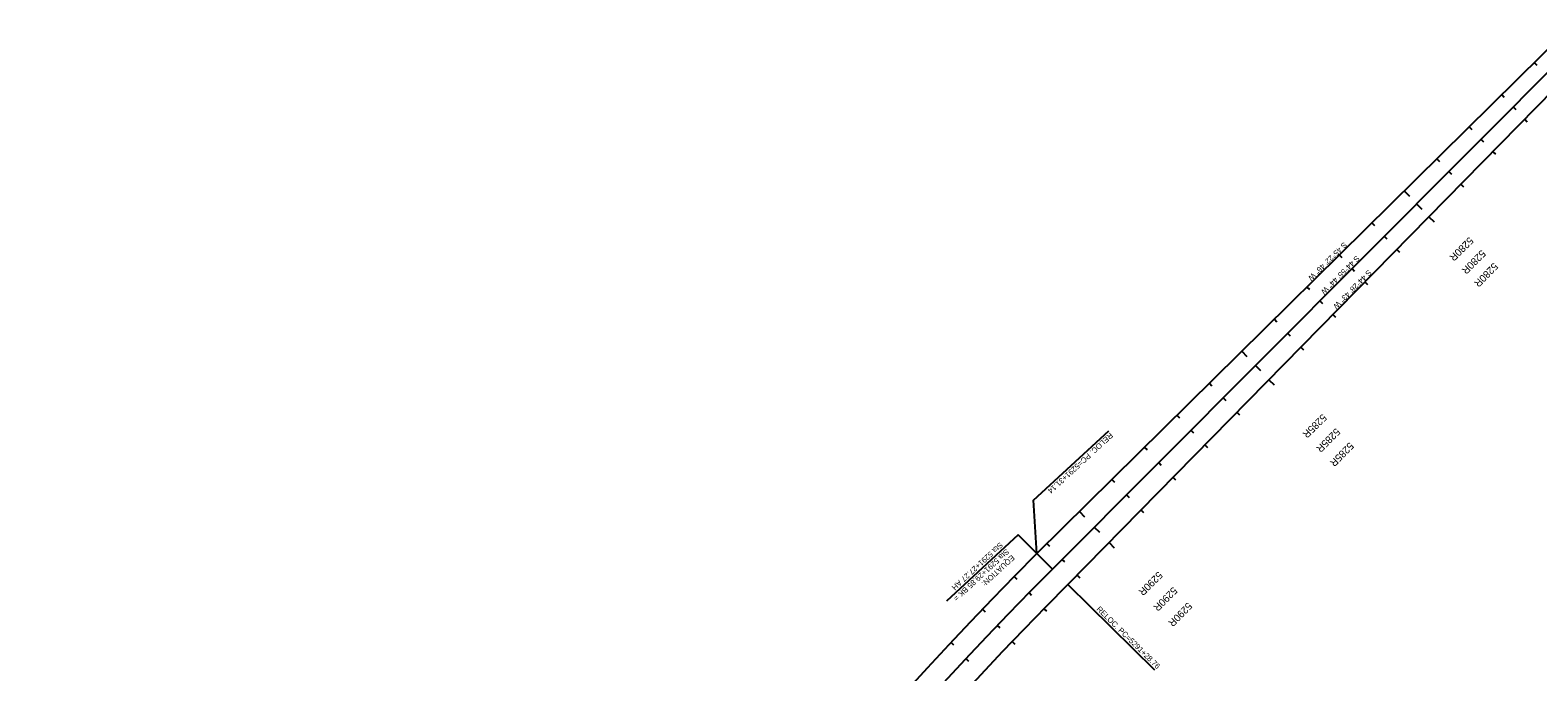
# Model space of a CAD drawing. Extents: x 2161211 to 2175594, y 601812 to 617732.
# Drawn here: x 2161211 to 2164514, y 605389 to 606794 of the extents above; entities that cross this region are included whole.
import ezdxf

# ---------------------------------------------------------------- set-up
doc = ezdxf.new("R2010")
doc.units = 0
for name, color, linetype in [('RD_HC_Cl', 7, 'Continuous'), ('RD_HC_CL_Rel', 7, 'Continuous'), ('RD_HC_Data_Rel', 7, 'Continuous'), ('RD_HC_Data_Tic', 7, 'Continuous'), ('RD_HC_Data_Tic_Rel', 7, 'Continuous'), ('RD_HC_TX_Rel_Sta50', 7, 'Continuous')]:
    doc.layers.add(name, color=color, linetype=linetype)

msp = doc.modelspace()

# ---------------------------------------------------------------- linework, layer by layer
at = {"layer": 'RD_HC_Cl'}
for radius in [8641.9, 8593.9, 8545.9]:
    msp.add_arc((2169535, 599544.7), radius, 135.07107, 164.41949, dxfattribs=at)
at = {"layer": 'RD_HC_CL_Rel'}
for p, q in [((2164578.5, 606794.4), (2163416.7, 605647.9)), ((2164603.4, 606769.6), (2163450.6, 605614)), ((2164628.3, 606744.8), (2163484.6, 605580.1))]:
    msp.add_line(p, q, dxfattribs=at)
at = {"layer": 'RD_HC_Data_Rel'}
for p, q in [((2163409.3, 605764.6), (2163574, 605916.7)), ((2163416.7, 605647.9), (2163409.3, 605764.6)), ((2163375.6, 605688.9), (2163218.6, 605543.9)), ((2163450.6, 605614), (2163375.6, 605688.9)), ((2163484.6, 605580.1), (2163674.7, 605393.5))]:
    msp.add_line(p, q, dxfattribs=at)
at = {"layer": 'RD_HC_Data_Tic'}
for p, q in [((2163366.9, 605597.6), (2163372.6, 605592)), ((2163399.5, 605562.3), (2163405.2, 605556.7)), ((2163297.3, 605525.8), (2163303, 605520.3)), ((2163432.1, 605527), (2163437.8, 605521.4)), ((2163329.9, 605490.5), (2163335.7, 605485)), ((2163228.5, 605453.3), (2163234.3, 605447.8)), ((2163362.5, 605455.2), (2163368.3, 605449.6)), ((2163261.1, 605417.9), (2163267, 605412.4))]:
    msp.add_line(p, q, dxfattribs=at)
at = {"layer": 'RD_HC_Data_Tic_Rel'}
for p, q in [((2164506.5, 606723.4), (2164512.1, 606717.7)), ((2164435.3, 606653.2), (2164440.9, 606647.5)), ((2164460.4, 606626.3), (2164466.1, 606620.7)), ((2164364.1, 606582.9), (2164369.8, 606577.2)), ((2164485.7, 606599.6), (2164491.4, 606593.9)), ((2164389.8, 606555.5), (2164395.5, 606549.9)), ((2164415.6, 606528.2), (2164421.3, 606522.6)), ((2164293, 606512.7), (2164298.6, 606507)), ((2164319.2, 606484.7), (2164324.9, 606479.1)), ((2164345.6, 606456.9), (2164351.3, 606451.2)), ((2164221.8, 606442.4), (2164233, 606431)), ((2164248.6, 606413.9), (2164259.9, 606402.6)), ((2164275.5, 606385.5), (2164286.9, 606374.3)), ((2164150.6, 606372.2), (2164156.2, 606366.5)), ((2164178, 606343.1), (2164183.6, 606337.5)), ((2164079.4, 606302), (2164085, 606296.3)), ((2164205.4, 606314.1), (2164211.1, 606308.5)), ((2164107.3, 606272.3), (2164113, 606266.7)), ((2164008.3, 606231.7), (2164013.9, 606226)), ((2164135.4, 606242.8), (2164141.1, 606237.2)), ((2164036.7, 606201.5), (2164042.4, 606195.9)), ((2163937.1, 606161.5), (2163942.7, 606155.8)), ((2164065.3, 606171.4), (2164071, 606165.8)), ((2163966.1, 606130.7), (2163971.8, 606125.1)), ((2163865.9, 606091.2), (2163877.1, 606079.8)), ((2163995.2, 606100.1), (2164000.9, 606094.5)), ((2163895.5, 606059.9), (2163906.8, 606048.6)), ((2163794.7, 606021), (2163800.3, 606015.3)), ((2163925.2, 606028.7), (2163936.6, 606017.5)), ((2163824.8, 605989.1), (2163830.5, 605983.5)), ((2163855.1, 605957.4), (2163860.8, 605951.8)), ((2163723.5, 605950.8), (2163729.2, 605945.1)), ((2163754.2, 605918.3), (2163759.9, 605912.7)), ((2163652.4, 605880.5), (2163658, 605874.8)), ((2163785, 605886), (2163790.7, 605880.4)), ((2163683.6, 605847.5), (2163689.3, 605841.9)), ((2163581.2, 605810.3), (2163586.8, 605804.6)), ((2163715, 605814.7), (2163720.7, 605809.1)), ((2163613, 605776.7), (2163618.6, 605771.1)), ((2163510, 605740), (2163521.2, 605728.6)), ((2163644.9, 605743.3), (2163650.6, 605737.7)), ((2163542.4, 605705.9), (2163553.7, 605694.6)), ((2163438.8, 605669.8), (2163444.4, 605664.1)), ((2163574.8, 605672), (2163586.3, 605660.8)), ((2163471.7, 605635.1), (2163477.4, 605629.5)), ((2163504.8, 605600.6), (2163510.5, 605595))]:
    msp.add_line(p, q, dxfattribs=at)

# ---------------------------------------------------------------- texts
at = {"layer": 'RD_HC_Data_Rel'}
for s, rotation, p in [('S 45°22\' 46" W', 224.6205, (2164089.1, 606331.2)), ('S 44°55\' 44" W', 225.0711, (2164116.8, 606301.7)), ('S 44°28\' 43" W', 225.5215, (2164142.9, 606270.4)), ('RELOC. PC=5291+31.14', 222.7195, (2163576.8, 605913.8)), ('Sta 5291+27.27 AH', 222.7195, (2163335.5, 605673.7)), ('Sta 5291+29.85 BK = ', 222.7195, (2163349.1, 605659)), ('EQUATION:', 222.7195, (2163361.3, 605645.8)), ('RELOC. PC=5291+28.76', 315.5215, (2163546.4, 605525.1))]:
    msp.add_text(s, height=12, rotation=rotation, dxfattribs=at).set_placement(p)
at = {"layer": 'RD_HC_TX_Rel_Sta50'}
for s, rotation, p in [('5280R', 224.6205, (2164364.1, 606342.6)), ('5280R', 225.0711, (2164390.8, 606314.3)), ('5280R', 225.5215, (2164417.6, 606286.2)), ('5285R', 224.6205, (2164042.4, 605954.9)), ('5285R', 225.0711, (2164071.9, 605923.9)), ('5285R', 225.5215, (2164101.5, 605893)), ('5290R', 224.6205, (2163682.8, 605609.8)), ('5290R', 225.0711, (2163715, 605576)), ('5290R', 225.5215, (2163747.4, 605542.3))]:
    msp.add_text(s, height=16, rotation=rotation, dxfattribs=at).set_placement(p)

doc.saveas('drawing.dxf')
